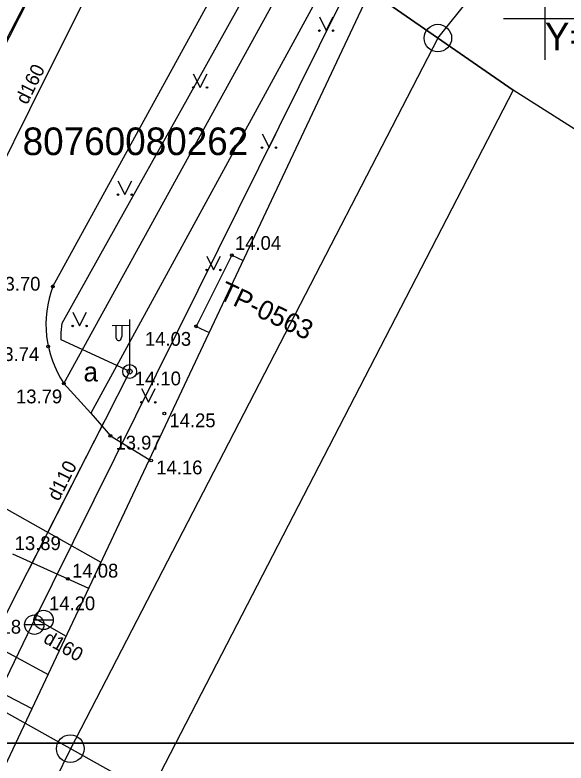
# Model space of a CAD drawing. Extents: x 503904 to 504094, y 304688 to 304960.
# Drawn here: x 504030.78 to 504050.77, y 304823.02 to 304850.13 of the extents above; entities that cross this region are included whole.
import ezdxf

# ---------------------------------------------------------------- set-up
doc = ezdxf.new("R2010")
doc.units = 0
for name, color, linetype in [('APGR_ELEM_####_####_#', 7, 'Continuous'), ('APGR_SARK_####_####_#', 7, 'Continuous'), ('APGS_ACRL_####_####_#', 7, 'Continuous'), ('APGS_ACRL_####_TKST_#', 7, 'Continuous'), ('APGS_ELEM_####_####_#', 7, 'Continuous'), ('APGS_VADP_ZSPR_####_#', 7, 'Continuous'), ('CELI_CMAL_####_####_#', 7, 'Continuous'), ('CELI_CSEG_####_TKST_#', 7, 'Continuous'), ('ELEK_STTP_####_####_#', 7, 'Continuous'), ('ELEK_STTP_####_TKST_#', 7, 'Continuous'), ('GAZE_VADP_VSP2_####_#', 7, 'Continuous'), ('GAZE_VADP_VSP2_TKST_#', 7, 'Continuous'), ('GEOD_ELEM_####_####_#', 7, 'Continuous'), ('GEOD_KORD_####_TKST_#', 7, 'Continuous'), ('RAMI_PLAN_####_TKST_#', 7, 'Continuous'), ('RAMI_UZMR_####_####_#', 7, 'Continuous'), ('RELJ_AATZ_####_TKST_#', 7, 'Continuous'), ('RELJ_ELEM_####_####_#', 7, 'Continuous'), ('ROBZ_UZMR_####_####_#', 7, 'Continuous'), ('ROBZ_UZMR_####_TKST_#', 7, 'Continuous'), ('SAKK_KKAN_####_####_#', 7, 'Continuous'), ('SKAN_VADP_PAST_####_I', 7, 'Continuous'), ('TERT_ELEM_####_####_#', 7, 'Continuous'), ('UDTK_ELEM_####_####_#', 7, 'Continuous'), ('UDTK_ELEM_####_TKST_#', 7, 'Continuous'), ('UDTK_VADP_UDEN_####_#', 7, 'Continuous'), ('UDTK_VADP_UDEN_TKST_#', 7, 'Continuous')]:
    doc.layers.add(name, color=color, linetype=linetype)

msp = doc.modelspace()

# ---------------------------------------------------------------- linework, layer by layer
at = {"layer": 'APGR_ELEM_####_####_#'}
for centre in [(504046.12, 304849.29), (504032.79, 304823.54)]:
    msp.add_circle(centre, 0.5, dxfattribs=at)
at = {"layer": 'APGR_SARK_####_####_#'}
for p, q in [((504046.119, 304849.289), (504060.581, 304867.489)), ((504046.119, 304849.289), (504032.794, 304823.54)), ((504032.794, 304823.54), (503998.701, 304752.902))]:
    msp.add_line(p, q, dxfattribs=at)
at = {"layer": 'APGS_ACRL_####_####_#'}
msp.add_lwpolyline([(504031.294, 304830.045), (504034.022, 304835.389)], dxfattribs=at)
at = {"layer": 'APGS_ELEM_####_####_#'}
for p, q in [((504034.944, 304837.207), (504034.944, 304839.09)), ((504034.944, 304838.874), (504034.309, 304838.869)), ((504034.444, 304838.87), (504034.444, 304838.478)), ((504034.654, 304838.872), (504034.654, 304838.478))]:
    msp.add_line(p, q, dxfattribs=at)
for radius in [0.25, 0.09]:
    msp.add_circle((504034.944, 304837.207), radius, dxfattribs=at)
msp.add_ellipse((504034.549, 304838.478), major_axis=(0, 0.151), ratio=0.695971, start_param=1.570796, end_param=4.712389, dxfattribs=at)
at = {"layer": 'APGS_VADP_ZSPR_####_#'}
for points in [[(504034.948, 304837.203), (504032.464, 304838.354), (504032.46, 304838.624), (504032.497, 304838.963), (504034.767, 304843.029), (504037.037, 304847.095), (504041.785, 304855.598), (504046.532, 304864.101), (504046.909, 304866.055), (504048.051, 304868.025), (504049.192, 304869.995), (504049.205, 304870.202), (504049.157, 304870.343), (504042.295, 304873.577), (504035.433, 304876.812), (504031.898, 304878.478), (504020.359, 304883.989), (504008.82, 304889.499), (504008.617, 304889.54), (504008.431, 304889.443), (504006.058, 304885.968)], [(504014.402, 304796.949), (504021.513, 304810.881), (504028.624, 304824.813), (504030.913, 304829.297), (504033.174, 304833.728), (504034.064, 304835.47), (504034.948, 304837.203)]]:
    msp.add_lwpolyline(points, dxfattribs=at)
at = {"layer": 'CELI_CMAL_####_####_#'}
for p, q in [((504033.541, 304835.699), (504032.559, 304836.774)), ((504033.541, 304835.699), (504034.244, 304834.88)), ((504034.244, 304834.88), (504035.656, 304834.023))]:
    msp.add_line(p, q, dxfattribs=at)
for points in [[(504043.505, 304874.98), (504041.235, 304870.26), (504033.948, 304855.96), (504026.066, 304840.762)], [(504032.161, 304840.294), (504039.525, 304853.703), (504045.705, 304864.823), (504050.845, 304874.537)], [(504032.559, 304836.774), (504041.261, 304852.587), (504047.431, 304863.915), (504052.724, 304873.608), (504051.009, 304874.521), (504050.882, 304874.598)], [(504054.623, 304874.25), (504048.611, 304863.3), (504042.44, 304852.018), (504033.541, 304835.699)], [(504030.694, 304830.598), (504033.454, 304829.352)]]:
    msp.add_lwpolyline(points, dxfattribs=at)
msp.add_arc((504035.756, 304838.918), 3.85, 159.0565, 213.8454, dxfattribs=at)
at = {"layer": 'ELEK_STTP_####_####_#'}
for points in [[(504038.653, 304841.421), (504037.351, 304838.845), (504037.824, 304838.622)], [(504038.653, 304841.421), (504039.055, 304841.231)]]:
    msp.add_lwpolyline(points, dxfattribs=at)
at = {"layer": 'GAZE_VADP_VSP2_####_#'}
for points in [[(504042.754, 304870.726), (504040.842, 304866.35), (504038.93, 304861.973), (504035.12, 304854.33), (504031.31, 304846.687), (504029.002, 304842.057), (504026.694, 304837.426), (504024.595, 304833.216), (504022.496, 304829.005), (504019.148, 304822.29), (504017.375, 304818.733), (504013.61, 304817.132), (504006.805, 304802.964), (504000, 304788.796), (503996.994, 304782.538), (503993.988, 304776.279), (503986.861, 304755.747)], [(504022.726, 304829.5), (504031.398, 304824.991)]]:
    msp.add_lwpolyline(points, dxfattribs=at)
at = {"layer": 'GEOD_ELEM_####_####_#'}
for p, q in [((504050, 304851.5), (504050, 304850)), ((504048.5, 304850), (504050, 304850)), ((504050, 304850), (504050, 304848.5)), ((504050, 304850), (504051.5, 304850))]:
    msp.add_line(p, q, dxfattribs=at)
at = {"layer": 'RAMI_PLAN_####_TKST_#'}
for points in [[(503904.204, 304959.85), (504093.703, 304959.85), (504093.703, 304823.741), (503904.204, 304823.741)], [(503904.204, 304823.741), (504093.703, 304823.741), (504093.703, 304687.633), (503904.204, 304687.633)]]:
    msp.add_lwpolyline(points, close=True, dxfattribs=at)
at = {"layer": 'RAMI_UZMR_####_####_#'}
msp.add_lwpolyline([(503923.253, 304801.015), (503981.982, 304759.672), (503995.48, 304748.813), (504027.75, 304817.255), (504060.02, 304885.696), (504048.875, 304885.773), (504036.803, 304888.853), (503994.536, 304908.303), (503981.123, 304894.75), (503978.518, 304892.436), (503950.886, 304846.726), (503923.253, 304801.015)], dxfattribs=at)
at = {"layer": 'RELJ_ELEM_####_####_#'}
for centre in [(504038.653, 304841.421), (504032.161, 304840.294), (504037.351, 304838.845), (504031.992, 304838.112), (504032.559, 304836.774), (504036.201, 304835.688), (504034.244, 304834.88), (504035.723, 304833.982), (504032.703, 304829.691)]:
    msp.add_circle(centre, 0.05, dxfattribs=at)
at = {"layer": 'ROBZ_UZMR_####_####_#'}
for points in [[(504052.953, 304844.812), (504048.85, 304847.4), (504030.463, 304860.121), (503981.123, 304894.75), (503968.011, 304904.031)], [(503976.684, 304743.679), (503981.982, 304759.672), (504030.463, 304860.121), (504048.85, 304847.4), (504035.67, 304821.93), (504026.069, 304827.305), (503995.067, 304763.071), (503986.854, 304740.353)]]:
    msp.add_lwpolyline(points, dxfattribs=at)
at = {"layer": 'SAKK_KKAN_####_####_#'}
msp.add_lwpolyline([(504021.091, 304832.416), (504025.241, 304830.023), (504029.39, 304827.63), (504031.983, 304826.233)], dxfattribs=at)
at = {"layer": 'SKAN_VADP_PAST_####_I'}
for points in [[(504023.783, 304835.985), (504032.733, 304853.578), (504047.208, 304883.667), (504054.39, 304883.114), (504058.648, 304882.787)], [(504023.783, 304835.985), (504030.293, 304832.324), (504033.899, 304830.296)]]:
    msp.add_lwpolyline(points, dxfattribs=at)
at = {"layer": 'TERT_ELEM_####_####_#'}
for p, q in [((504041.823, 304850.06), (504042.073, 304849.56)), ((504042.073, 304849.56), (504042.323, 304850.06)), ((504037.25, 304848), (504037.5, 304847.5)), ((504037.5, 304847.5), (504037.75, 304848)), ((504039.747, 304845.821), (504039.997, 304845.321)), ((504039.997, 304845.321), (504040.247, 304845.821)), ((504034.52, 304844.118), (504034.77, 304843.618)), ((504034.77, 304843.618), (504035.02, 304844.118)), ((504037.737, 304841.389), (504037.987, 304840.889)), ((504037.987, 304840.889), (504038.237, 304841.389)), ((504032.879, 304839.359), (504033.129, 304838.859)), ((504033.129, 304838.859), (504033.379, 304839.359)), ((504035.371, 304836.592), (504035.621, 304836.092)), ((504035.621, 304836.092), (504035.871, 304836.592))]:
    msp.add_line(p, q, dxfattribs=at)
for centre, radius in [((504041.823, 304849.56), 0.028), ((504042.323, 304849.56), 0.0263), ((504037.25, 304847.5), 0.028), ((504037.75, 304847.5), 0.0263), ((504039.746, 304845.32), 0.028), ((504040.246, 304845.32), 0.0263), ((504034.52, 304843.617), 0.028), ((504035.02, 304843.617), 0.0263), ((504037.736, 304840.888), 0.028), ((504038.236, 304840.888), 0.0263), ((504032.879, 304838.858), 0.028), ((504033.379, 304838.858), 0.0263), ((504035.371, 304836.091), 0.028), ((504035.871, 304836.091), 0.0263)]:
    msp.add_circle(centre, radius, dxfattribs=at)
at = {"layer": 'UDTK_ELEM_####_####_#'}
for p, q in [((504031.472, 304828.205), (504032.174, 304828.205)), ((504031.134, 304828.035), (504031.836, 304828.035))]:
    msp.add_line(p, q, dxfattribs=at)
for centre in [(504031.485, 304828.035), (504031.823, 304828.205)]:
    msp.add_circle(centre, 0.351, dxfattribs=at)
at = {"layer": 'UDTK_VADP_UDEN_####_#'}
for points in [[(504052.599, 304884.688), (504054.563, 304874.709), (504047.684, 304860.837), (504037.414, 304840.144), (504031.385, 304827.996), (504014.788, 304793.579), (504000, 304762.914), (503998.944, 304760.723), (503997.887, 304758.532), (503994.035, 304750.096), (503993.994, 304750.008)], [(504031.514, 304828.255), (504032.638, 304827.622)]]:
    msp.add_lwpolyline(points, dxfattribs=at)

# ---------------------------------------------------------------- texts
at = {"layer": 'APGS_ACRL_####_TKST_#'}
msp.add_text('d110', height=0.5, rotation=62.9566, dxfattribs=at).set_placement((504032.37, 304832.483))
at = {"layer": 'CELI_CSEG_####_TKST_#'}
msp.add_text('a', height=0.7, dxfattribs=at).set_placement((504033.27, 304836.848))
at = {"layer": 'ELEK_STTP_####_TKST_#'}
msp.add_text('TP-0563', height=0.7, rotation=334.7563, dxfattribs=at).set_placement((504038.131, 304839.866))
at = {"layer": 'GAZE_VADP_VSP2_TKST_#'}
msp.add_text('d160', height=0.5, rotation=63.5039, dxfattribs=at).set_placement((504031.224, 304846.85))
at = {"layer": 'GEOD_KORD_####_TKST_#'}
msp.add_text('Y=504050', height=1, dxfattribs=at).set_placement((504050, 304848.85))
at = {"layer": 'RELJ_AATZ_####_TKST_#'}
for s, p in [(' 14.04', (504038.575, 304841.617)), (' 13.70', (504029.848, 304840.138)), (' 14.03', (504035.313, 304838.14)), (' 13.74', (504029.804, 304837.589)), (' 14.10', (504034.944, 304836.707)), (' 13.79', (504030.636, 304836.055)), (' 14.25', (504036.201, 304835.188)), (' 13.97', (504034.244, 304834.38)), (' 14.16', (504035.723, 304833.482)), (' 13.89', (504030.587, 304830.737)), (' 14.08', (504032.672, 304829.741))]:
    msp.add_text(s, height=0.5, dxfattribs=at).set_placement(p)
at = {"layer": 'ROBZ_UZMR_####_TKST_#'}
msp.add_text('80760080262', height=1, dxfattribs=at).set_placement((504031.063, 304845.051))
at = {"layer": 'UDTK_ELEM_####_TKST_#'}
for s, p in [('14.20', (504032.021, 304828.556)), ('14.18', (504029.333, 304827.708))]:
    msp.add_text(s, height=0.5, dxfattribs=at).set_placement(p)
at = {"layer": 'UDTK_VADP_UDEN_TKST_#'}
msp.add_text('d160', height=0.5, rotation=330.6242, dxfattribs=at).set_placement((504031.778, 304827.408))

doc.saveas('drawing.dxf')
